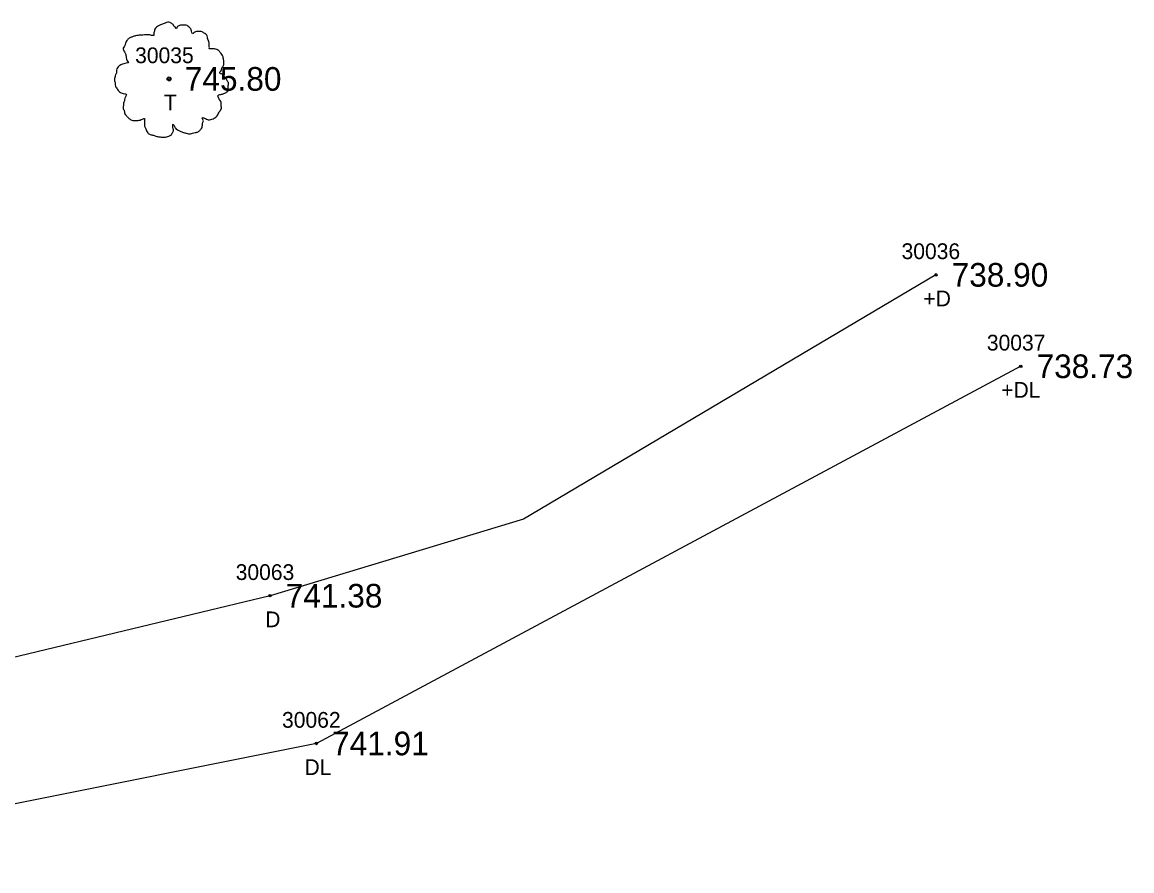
# Model space of a CAD drawing. Extents: x 1375131 to 1378678, y 999028 to 1004053.
# Drawn here: x 1376809.2 to 1376879.7, y 1002795.2 to 1002849.1 of the extents above; entities that cross this region are included whole.
import ezdxf

# ---------------------------------------------------------------- set-up
doc = ezdxf.new("R2010")
doc.units = 0
for name, color, linetype in [('RD_EX_Driveway', 7, 'Continuous'), ('RD_EX_Driveway_txCode', 7, 'Continuous'), ('RD_EX_TX_Driveway_ELEV', 7, 'Continuous'), ('RD_EX_TX_VEG_ELEV', 7, 'Continuous'), ('RD_EX_VEG', 7, 'Continuous'), ('RD_EX_VEG_txCode', 7, 'Continuous'), ('RD_SMD_Locator', 7, 'Continuous')]:
    doc.layers.add(name, color=color, linetype=linetype)

msp = doc.modelspace()

# ---------------------------------------------------------------- linework, layer by layer
at = {"layer": 'RD_EX_Driveway'}
for points in [[(1376867.236, 1002833.08), (1376841.055, 1002817.567), (1376824.956, 1002812.704), (1376785.489, 1002803.207)], [(1376872.628, 1002827.274), (1376827.899, 1002803.322), (1376787.501, 1002795.238)]]:
    msp.add_lwpolyline(points, dxfattribs=at)
at = {"layer": 'RD_EX_VEG'}
for centre, radius in [((1376818.546, 1002845.521), 0.125), ((1376818.54, 1002845.512), 0.00005)]:
    msp.add_circle(centre, radius, dxfattribs=at)
for points in [[(1376818.612, 1002849.105), (1376818.462, 1002849.117), (1376818.3, 1002849.067), (1376818.175, 1002849.017), (1376818.062, 1002848.98), (1376817.95, 1002848.93), (1376817.8, 1002848.842), (1376817.687, 1002848.742), (1376817.625, 1002848.617), (1376817.6, 1002848.505), (1376817.575, 1002848.367), (1376817.575, 1002848.28), (1376817.512, 1002848.267), (1376817.437, 1002848.28), (1376817.313, 1002848.317), (1376817.188, 1002848.317), (1376817.063, 1002848.317), (1376816.888, 1002848.305), (1376816.713, 1002848.305), (1376816.575, 1002848.28), (1376816.413, 1002848.255), (1376816.226, 1002848.193), (1376816.051, 1002848.13), (1376815.901, 1002848.005), (1376815.776, 1002847.768), (1376815.713, 1002847.593), (1376815.638, 1002847.468), (1376815.713, 1002847.243), (1376815.801, 1002847.068), (1376815.813, 1002846.968), (1376815.851, 1002846.756), (1376815.901, 1002846.643), (1376815.963, 1002846.543), (1376815.926, 1002846.531), (1376815.738, 1002846.506), (1376815.588, 1002846.456), (1376815.376, 1002846.343), (1376815.263, 1002846.231), (1376815.213, 1002846.068), (1376815.201, 1002845.894), (1376815.151, 1002845.794), (1376815.114, 1002845.656), (1376815.101, 1002845.619), (1376815.076, 1002845.456), (1376815.126, 1002845.231), (1376815.139, 1002845.056), (1376815.201, 1002844.944), (1376815.276, 1002844.857), (1376815.363, 1002844.732), (1376815.563, 1002844.619), (1376815.726, 1002844.569), (1376815.826, 1002844.557), (1376815.738, 1002844.307), (1376815.713, 1002844.132), (1376815.651, 1002843.932), (1376815.651, 1002843.894), (1376815.626, 1002843.657), (1376815.701, 1002843.495), (1376815.738, 1002843.307), (1376815.826, 1002843.195), (1376815.963, 1002843.045), (1376816.126, 1002842.932), (1376816.375, 1002842.87), (1376816.575, 1002842.882), (1376816.863, 1002842.97), (1376816.988, 1002843.007), (1376816.975, 1002842.92), (1376816.988, 1002842.732), (1376816.988, 1002842.52), (1376817.063, 1002842.358), (1376817.113, 1002842.22), (1376817.188, 1002842.095), (1376817.35, 1002841.983), (1376817.55, 1002841.945), (1376817.762, 1002841.87), (1376817.987, 1002841.833), (1376818.237, 1002841.82), (1376818.537, 1002841.895), (1376818.674, 1002841.958), (1376818.724, 1002842.045), (1376818.824, 1002842.233), (1376818.799, 1002842.345), (1376818.812, 1002842.645), (1376818.862, 1002842.557), (1376818.949, 1002842.383), (1376819.199, 1002842.233), (1376819.399, 1002842.145), (1376819.637, 1002842.07), (1376819.786, 1002842.033), (1376820.024, 1002842.07), (1376820.211, 1002842.108), (1376820.399, 1002842.17), (1376820.549, 1002842.308), (1376820.636, 1002842.445), (1376820.661, 1002842.582), (1376820.699, 1002842.77), (1376820.724, 1002842.857)], [(1376820.724, 1002842.857), (1376820.686, 1002842.945), (1376820.661, 1002843.07), (1376820.699, 1002843.057), (1376820.786, 1002843.032), (1376820.923, 1002842.97), (1376821.036, 1002842.932), (1376821.198, 1002842.945), (1376821.336, 1002842.995), (1376821.561, 1002843.132), (1376821.698, 1002843.37), (1376821.836, 1002843.57), (1376821.873, 1002843.732), (1376821.848, 1002843.844), (1376821.836, 1002844.094), (1376821.736, 1002844.219), (1376821.711, 1002844.282), (1376821.661, 1002844.482), (1376821.698, 1002844.507), (1376821.836, 1002844.532), (1376822.023, 1002844.594), (1376822.16, 1002844.657), (1376822.273, 1002844.744), (1376822.31, 1002844.857), (1376822.298, 1002845.056), (1376822.323, 1002845.256), (1376822.285, 1002845.331), (1376822.235, 1002845.406), (1376822.198, 1002845.506), (1376822.123, 1002845.581), (1376822.073, 1002845.656), (1376822.023, 1002845.706), (1376821.961, 1002845.781), (1376821.873, 1002845.844), (1376821.798, 1002845.869), (1376821.773, 1002845.944), (1376821.848, 1002846.043), (1376821.873, 1002846.093), (1376821.886, 1002846.206), (1376821.998, 1002846.381), (1376822.023, 1002846.581), (1376821.998, 1002846.793), (1376821.973, 1002846.931), (1376821.898, 1002847.068), (1376821.798, 1002847.193), (1376821.736, 1002847.28), (1376821.648, 1002847.343), (1376821.486, 1002847.405), (1376821.361, 1002847.43), (1376821.186, 1002847.43), (1376821.086, 1002847.455), (1376821.098, 1002847.48), (1376821.098, 1002847.555), (1376821.098, 1002847.693), (1376821.061, 1002847.918), (1376820.986, 1002848.168), (1376820.986, 1002848.18), (1376820.936, 1002848.305), (1376820.824, 1002848.405), (1376820.736, 1002848.455), (1376820.636, 1002848.517), (1376820.511, 1002848.53), (1376820.361, 1002848.53), (1376820.224, 1002848.505), (1376820.124, 1002848.455), (1376820.036, 1002848.392), (1376819.999, 1002848.467), (1376819.949, 1002848.617), (1376819.924, 1002848.692), (1376819.849, 1002848.78), (1376819.737, 1002848.88), (1376819.512, 1002848.942), (1376819.199, 1002848.905), (1376819.049, 1002848.805), (1376818.974, 1002848.717), (1376818.949, 1002848.78), (1376818.849, 1002848.88), (1376818.799, 1002848.967), (1376818.712, 1002849.03), (1376818.637, 1002849.08), (1376818.587, 1002849.105)]]:
    msp.add_spline(points, degree=3, dxfattribs=at)
at = {"layer": 'RD_SMD_Locator'}
for centre in [(1376818.546, 1002845.521), (1376867.236, 1002833.08), (1376872.628, 1002827.274), (1376824.956, 1002812.704), (1376827.899, 1002803.322)]:
    msp.add_circle(centre, 0.075, dxfattribs=at)

# ---------------------------------------------------------------- texts
at = {"layer": 'RD_EX_Driveway_txCode'}
for s, p in [('30036', (1376865.055, 1002834.08)), ('+D', (1376866.441, 1002831.08)), ('30037', (1376870.471, 1002828.274)), ('+DL', (1376871.384, 1002825.274)), ('30063', (1376822.775, 1002813.704)), ('D', (1376824.649, 1002810.704)), ('30062', (1376825.718, 1002804.322)), ('DL', (1376827.143, 1002801.322))]:
    msp.add_text(s, height=1, dxfattribs=at).set_placement(p)
at = {"layer": 'RD_EX_TX_Driveway_ELEV'}
for s, p in [('738.90', (1376868.236, 1002832.33)), ('738.73', (1376873.628, 1002826.524)), ('741.38', (1376825.956, 1002811.954)), ('741.91', (1376828.899, 1002802.572))]:
    msp.add_text(s, height=1.5, dxfattribs=at).set_placement(p)
at = {"layer": 'RD_EX_TX_VEG_ELEV'}
msp.add_text('745.80', height=1.5, dxfattribs=at).set_placement((1376819.546, 1002844.771))
at = {"layer": 'RD_EX_VEG_txCode'}
for s, p in [('30035', (1376816.389, 1002846.521)), ('T', (1376818.223, 1002843.521))]:
    msp.add_text(s, height=1, dxfattribs=at).set_placement(p)

doc.saveas('drawing.dxf')
